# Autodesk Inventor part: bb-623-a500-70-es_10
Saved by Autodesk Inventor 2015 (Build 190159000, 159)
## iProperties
Created: 2022-04
Part Number: bb-623-a500-70-es_10
Checked By: TraceParts S.A.
Material: Generic
Catalog Web Link: www.traceparts.com
Document SubType Name: Modeling
Designer: TraceParts
Density: 1 g/cm^3
Appearance: Default
Company: TraceParts S.A.
Author: TraceParts
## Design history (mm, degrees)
feature "bb-623-a500-70-es_10.ipt"
body "Solid1"
